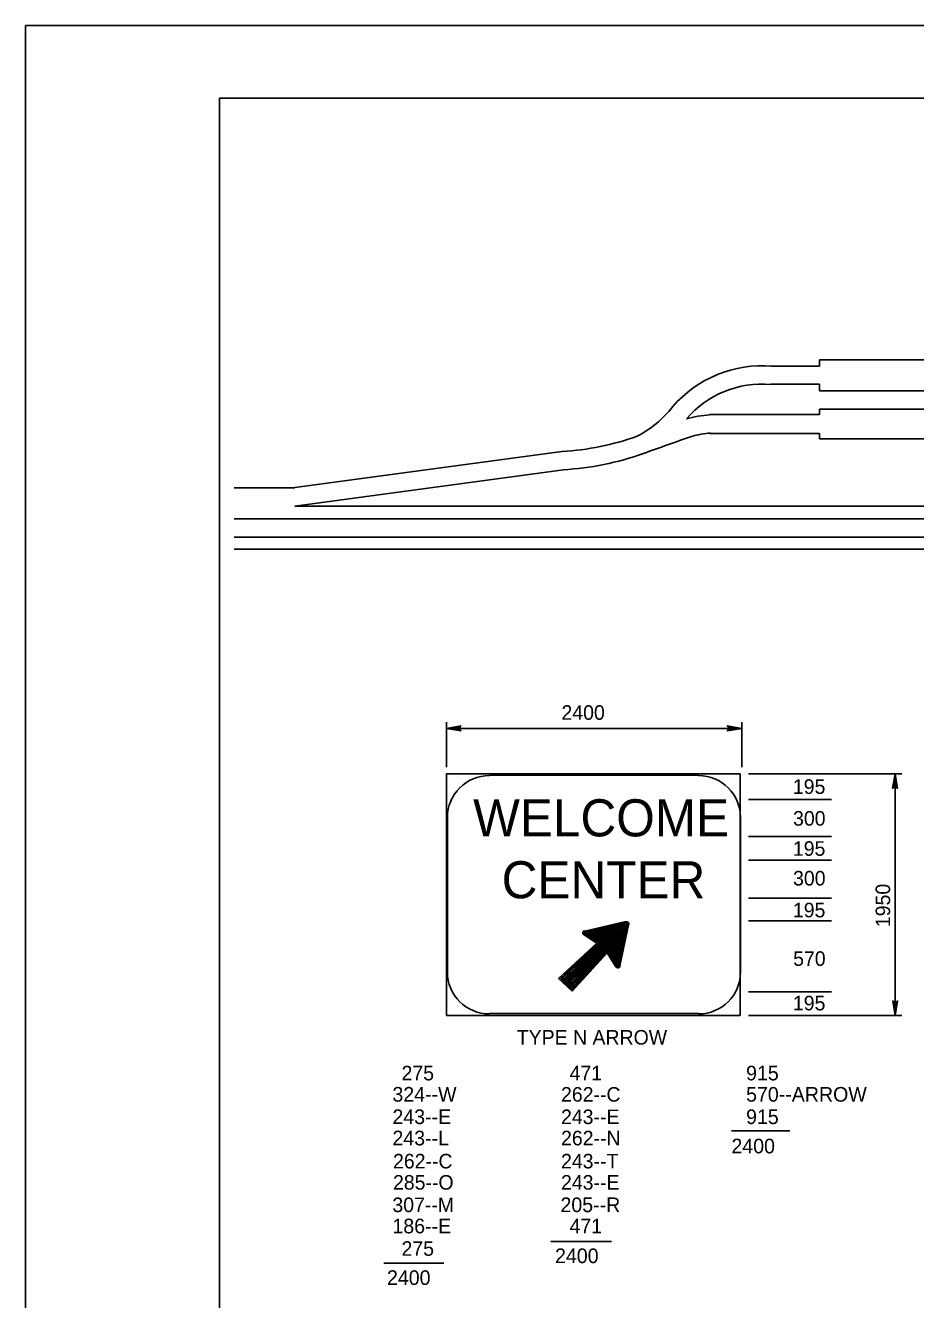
# Model space of a CAD drawing. Extents: x 638689 to 652291, y 298458 to 299646.
# Drawn here: x 651386.3 to 651569.7, y 299383.4 to 299645.7 of the extents above; entities that cross this region are included whole.
import ezdxf

# ---------------------------------------------------------------- set-up
doc = ezdxf.new("R2010")
doc.units = 0
for name, color, linetype in [('1', 7, 'Continuous'), ('2', 7, 'Continuous'), ('3', 7, 'Continuous'), ('PLT-BNDY', 7, 'Continuous')]:
    doc.layers.add(name, color=color, linetype=linetype)

# ---------------------------------------------------------------- blocks, each defined once
blk = doc.blocks.new('RARROW')
at = {"layer": '3'}
blk.add_lwpolyline([(-2.2695, 0.285), (-2.184875, 0.12075), (0, 0), (-2.2695, 0.285), (-2.38575, 0.384625), (0, 0), (-2.183125, -0.108), (-2.262875, -0.2705), (0, 0), (-2.38575, -0.379125), (-2.262875, -0.2705)], dxfattribs=at)

msp = doc.modelspace()

# ---------------------------------------------------------------- linework, layer by layer
at = {"layer": '1'}
for q in [(652212.31, 299630.75), (651426.31, 299066.75)]:
    msp.add_line((651426.31, 299630.75), q, dxfattribs=at)
at = {"layer": '2'}
for p, q in [((651539.94, 299575.62), (651549.94, 299575.62)), ((651549.94, 299576.87), (651572.56, 299576.87)), ((651549.94, 299575.62), (651549.94, 299576.87)), ((651539.94, 299571.87), (651549.94, 299571.87)), ((651549.94, 299570.5), (651549.94, 299571.87)), ((651549.94, 299570.5), (651572.56, 299570.5)), ((651527.31, 299565.62), (651549.94, 299565.62)), ((651549.94, 299566.75), (651572.56, 299566.75)), ((651549.94, 299566.75), (651549.94, 299565.62)), ((651527.31, 299561.75), (651549.94, 299561.75)), ((651549.94, 299561.75), (651549.94, 299560.62)), ((651549.94, 299560.62), (651572.56, 299560.62)), ((651441.31, 299550.5), (651496.81, 299558)), ((651441.81, 299546.75), (651497.19, 299554.25)), ((651497.19, 299554.25), (651497.19, 299554.25)), ((651497.19, 299554.25), (651497.19, 299554.25)), ((651441.81, 299550.5), (651429.31, 299550.5)), ((651441.81, 299546.75), (651680.69, 299546.75)), ((651441.81, 299546.75), (651441.81, 299546.75)), ((651441.81, 299546.75), (651441.81, 299546.75)), ((651429.31, 299544.12), (652211.31, 299544.12)), ((651429.31, 299540.37), (652211.31, 299540.37)), ((651429.31, 299537.87), (652211.31, 299537.87)), ((651473.06, 299493), (651473.06, 299502.25)), ((651533.94, 299493), (651533.94, 299502.25)), ((651473.06, 299501), (651533.94, 299501)), ((651535.31, 299491.62), (651566.9, 299491.62)), ((651565.52, 299441.87), (651565.52, 299491.62)), ((651535.31, 299486.37), (651552.39, 299486.37)), ((651473.31, 299482.75), (651473.31, 299450.75)), ((651533.69, 299450.75), (651533.69, 299482.75)), ((651535.31, 299478.75), (651552.39, 299478.75)), ((651535.31, 299473.87), (651552.39, 299473.87)), ((651535.31, 299466), (651552.39, 299466)), ((651510.06, 299461.25), (651501.56, 299459.25)), ((651508.81, 299452.12), (651510.56, 299460.5)), ((651510.69, 299461.37), (651510.69, 299461.37)), ((651535.31, 299461.37), (651552.39, 299461.37)), ((651500.56, 299459.12), (651500.56, 299459.12)), ((651501.44, 299458.5), (651504.06, 299456.75)), ((651504.06, 299456.75), (651496.19, 299449.5)), ((651498.94, 299446.87), (651506.19, 299454.75)), ((651504.06, 299456.75), (651504.06, 299456.75)), ((651506.19, 299454.75), (651506.19, 299454.75)), ((651506.19, 299454.75), (651507.94, 299451.87)), ((651496.19, 299449.5), (651498.94, 299446.87)), ((651508.56, 299450.87), (651508.56, 299450.87)), ((651535.31, 299446.75), (651552.39, 299446.75)), ((651535.31, 299441.87), (651566.9, 299441.87))]:
    msp.add_line(p, q, dxfattribs=at)
msp.add_lwpolyline([(651473.06, 299441.87), (651473.06, 299491.62), (651533.56, 299491.62), (651533.56, 299441.87)], close=True, dxfattribs=at)
for points in [[(651525.06, 299491.37), (651481.94, 299491.37)], [(651496.31, 299449.62), (651504.44, 299456.87), (651501.44, 299458.75), (651501.31, 299458.87), (651501.56, 299459.25), (651510.19, 299461.12), (651510.56, 299461), (651510.56, 299460.62), (651508.69, 299452.12), (651508.44, 299451.87), (651508.06, 299452), (651506.19, 299454.87), (651498.94, 299447), (651496.56, 299449.5), (651504.56, 299456.87), (651501.44, 299458.87), (651501.44, 299458.87), (651501.56, 299459.25), (651510.19, 299461), (651510.31, 299460.87), (651510.44, 299460.62), (651508.56, 299452.25), (651508.31, 299452), (651508.06, 299452), (651506.19, 299455), (651498.81, 299447.12), (651496.69, 299449.5), (651504.69, 299456.75), (651501.56, 299458.87), (651501.56, 299459), (651501.56, 299459.12), (651510.31, 299460.75), (651508.31, 299452.12), (651506.19, 299455.25), (651498.81, 299447.25), (651496.94, 299449.5), (651504.69, 299456.75), (651501.56, 299459), (651510.19, 299460.62)], [(651501.69, 299458.87), (651510.19, 299460.5), (651508.31, 299452.25), (651506.19, 299455.62), (651498.69, 299447.37), (651497.06, 299449.5), (651504.81, 299456.87), (651502.19, 299458.87), (651509.94, 299460.37), (651508.19, 299452.5), (651506.31, 299455.87), (651498.69, 299447.75), (651497.44, 299449.5), (651505.06, 299456.87), (651502.69, 299458.75), (651509.69, 299460.12), (651508.06, 299453), (651506.31, 299456), (651498.69, 299447.87), (651497.69, 299449.62), (651505.19, 299456.87), (651503.19, 299458.62), (651509.56, 299460), (651507.94, 299453.5), (651506.31, 299456.12), (651498.81, 299448.25), (651497.94, 299449.62), (651505.44, 299456.87), (651503.56, 299458.5), (651509.31, 299459.62), (651507.94, 299453.87), (651506.31, 299456.37), (651498.81, 299448.62), (651498.31, 299449.62), (651505.56, 299456.87), (651503.94, 299458.37), (651509.06, 299459.37), (651507.81, 299454.37), (651506.31, 299456.5), (651498.94, 299449.12), (651498.81, 299449), (651498.44, 299449.5), (651505.81, 299456.87), (651504.44, 299458.25), (651508.81, 299459.25), (651507.56, 299454.75), (651506.31, 299456.62), (651498.81, 299449.12), (651498.56, 299449.5), (651506.06, 299456.87), (651504.81, 299458.25), (651508.44, 299459), (651507.56, 299455.25), (651506.31, 299456.87), (651498.69, 299449.25), (651498.69, 299449.5), (651506.19, 299456.87), (651505.06, 299458.12), (651508.31, 299458.87), (651507.56, 299455.5), (651505.44, 299458), (651508.06, 299458.62), (651507.44, 299455.87), (651505.81, 299458), (651507.81, 299458.25), (651507.31, 299456), (651506.06, 299457.75), (651507.56, 299458.12), (651507.31, 299456.5), (651506.44, 299457.62), (651507.44, 299458), (651507.19, 299456.87), (651506.81, 299457.5), (651507.19, 299457.62), (651507.06, 299457.25)], [(651481.94, 299442.25), (651525.06, 299442.25)]]:
    msp.add_lwpolyline(points, dxfattribs=at)
for centre, radius, start, end in [((651538.2, 299551.14), 24.54, 85.4134, 139.1043), ((651538.2, 299551.14), 20.77, 85.4134, 139.1043), ((651502.66, 299580.34), 21.48, 296.8793, 322.3109), ((651528.36, 299544.96), 20.62, 92.9526, 106.4866), ((651493.68, 299613.5), 55.58, 273.3346, 289.6636), ((654118.4, 292218.64), 7787.51, 109.463364, 109.540836), ((651528.36, 299544.96), 16.85, 92.9526, 106.4866), ((651493.68, 299613.5), 59.35, 273.3346, 289.6636), ((651481.91, 299482.64), 8.64, 90, 180), ((651525.03, 299482.64), 8.64, 0, 90), ((651510.17, 299460.71), 0.477, 348.0958, 101.9043), ((651510.17, 299460.71), 0.477, 348.0958, 101.9043), ((651501.62, 299458.9), 0.477, 101.9042, 237.308), ((651501.62, 299458.9), 0.477, 101.9043, 237.308), ((651481.91, 299450.82), 8.64, 180, 270), ((651508.37, 299452.16), 0.477, 212.692, 348.0958), ((651508.37, 299452.16), 0.477, 212.692, 348.0958), ((651525.03, 299450.82), 8.64, 270, 0)]:
    msp.add_arc(centre, radius, start, end, dxfattribs=at)
at = {"layer": '3'}
for p, q in [((651531.8, 299418.12), (651543.8, 299418.12)), ((651494.56, 299395.29), (651507.06, 299395.29)), ((651460.19, 299390.87), (651472.56, 299390.87))]:
    msp.add_line(p, q, dxfattribs=at)
at = {"layer": 'PLT-BNDY'}
msp.add_lwpolyline([(651386.31, 299645.75), (652227.31, 299645.75), (652227.31, 299051.75), (651386.31, 299051.75)], close=True, dxfattribs=at)

# ---------------------------------------------------------------- block references
at = {"layer": '2', "xscale": 1.2574347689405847, "yscale": 1.3092961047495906}
for p, rotation in [((651473.06, 299501), 180), ((651565.52, 299491.62), 89.99999999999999), ((651565.52, 299441.87), -90.00000000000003)]:
    msp.add_blockref('RARROW', p, dxfattribs=dict(at, rotation=rotation))
msp.add_blockref('RARROW', (651533.94, 299501), dxfattribs=at)

# ---------------------------------------------------------------- texts
at = {"layer": '2'}
for s, height, p in [('2400', 3, (651496.77, 299502.76)), ('195', 3, (651544.46, 299487.5)), ('WELCOME', 7.634, (651478.56, 299478.75)), ('300', 3, (651544.49, 299480.96)), ('195', 3, (651544.46, 299474.75)), ('CENTER', 7.634, (651484.44, 299466)), ('300', 3, (651544.49, 299468.63)), ('195', 3, (651544.46, 299462.08)), ('570', 3, (651544.51, 299452.08)), ('195', 3, (651544.46, 299442.92)), ('TYPE N ARROW', 3, (651487.56, 299435.87)), ('275  ', 3, (651463.81, 299428.5)), ('471    ', 3, (651498.44, 299428.5)), ('915       ', 3.016, (651534.81, 299428.5)), (' 324--W', 3.016, (651460.81, 299424.12)), (' 262--C', 3, (651495.56, 299424.12)), ('570--ARROW', 3.016, (651534.81, 299424.12)), (' 243--E', 3.016, (651460.81, 299419.5)), (' 243--E', 3, (651495.56, 299419.5)), ('915       ', 3.016, (651534.81, 299419.5)), (' 243--L', 3.016, (651460.81, 299415.12)), (' 262--N', 3, (651495.56, 299415.12)), ('2400        ', 3.0158, (651531.79, 299413.47)), (' 262--C', 3, (651460.94, 299410.37)), (' 243--T', 3, (651495.56, 299410.37)), (' 285--O', 3, (651460.94, 299406)), (' 243--E', 3, (651495.56, 299406)), (' 307--M', 3, (651460.81, 299401.37)), (' 205--R', 3.016, (651495.44, 299401.37)), (' 186--E', 3.016, (651460.81, 299397)), ('471    ', 3, (651498.44, 299397)), ('275  ', 3, (651463.81, 299392.37)), ('2400     ', 3.016, (651495.44, 299390.87)), ('2400   ', 3.016, (651460.81, 299386.37))]:
    msp.add_text(s, height=height, dxfattribs=at).set_placement(p)
msp.add_text('1950', height=3, rotation=90, dxfattribs=at).set_placement((651564.5, 299460.06))

doc.saveas('drawing.dxf')
